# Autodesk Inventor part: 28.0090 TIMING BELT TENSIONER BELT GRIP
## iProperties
Created: 2007-04
Part Number: 28.0090 TIMING BELT TENSIONER BELT GRIP
Material: Aluminum-6061
Document SubType Name: Modeling
Designer: Andy Moles
Density: 2.71 g/cm^3
Author: Andy Moles
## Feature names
1. Extrusion1
2. Extrusion2
